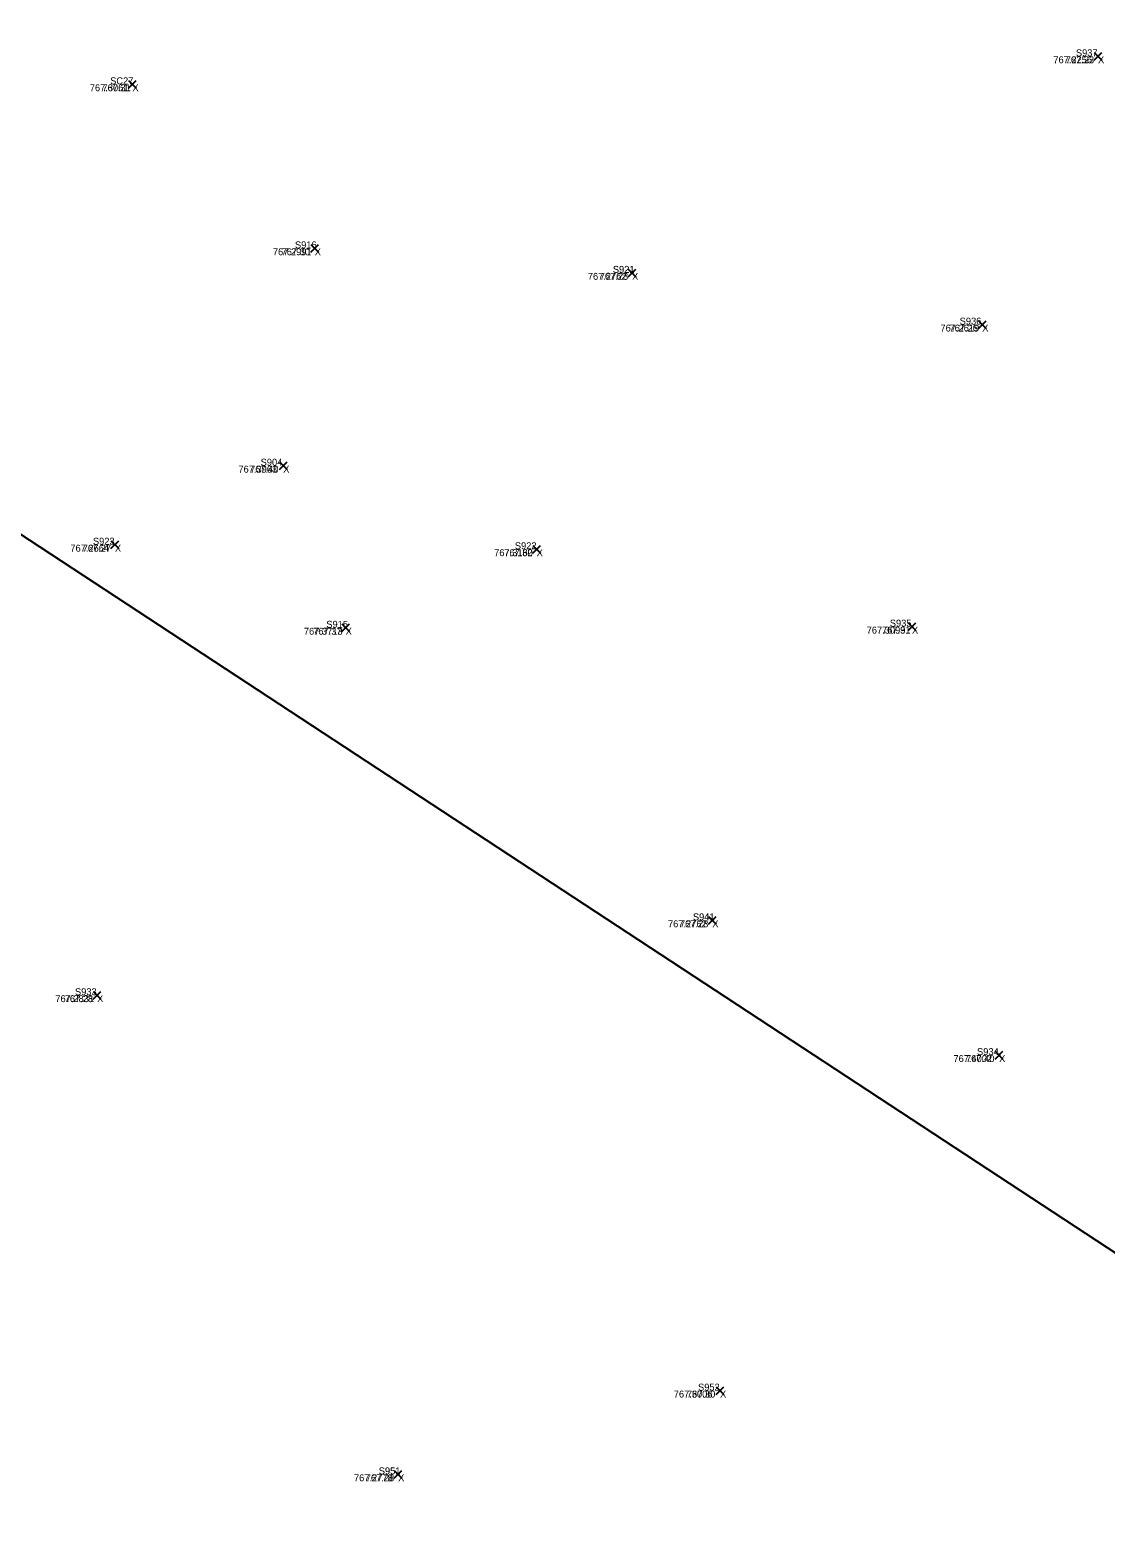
# Model space of a CAD drawing. Extents: x 1845019 to 1877956, y 680444 to 701081.
# Drawn here: x 1857694.08 to 1857703.38, y 694251.31 to 694264.34 of the extents above; entities that cross this region are included whole.
import ezdxf

# ---------------------------------------------------------------- set-up
doc = ezdxf.new("R2010")
doc.units = 0
for name, color, linetype in [('SV_X_CL_Survey_20', 7, 'Continuous'), ('SV_X_Random_Point', 7, 'Continuous'), ('SV_X_Text_Comment', 7, 'Continuous'), ('SV_X_Text_Elevation', 7, 'Continuous'), ('SV_X_Text_Name', 7, 'Continuous')]:
    doc.layers.add(name, color=color, linetype=linetype)

msp = doc.modelspace()

# ---------------------------------------------------------------- linework, layer by layer
at = {"layer": 'SV_X_CL_Survey_20'}
msp.add_line((1856038.267, 695346.314), (1858797.327, 693536.085), dxfattribs=at)
at = {"layer": 'SV_X_Random_Point'}
for p, q in [((1857703.277, 694264.085), (1857703.344, 694264.152)), ((1857703.277, 694264.152), (1857703.344, 694264.085)), ((1857703.277, 694264.085), (1857703.344, 694264.152)), ((1857703.277, 694264.152), (1857703.344, 694264.085)), ((1857694.927, 694263.843), (1857694.994, 694263.909)), ((1857694.927, 694263.909), (1857694.994, 694263.843)), ((1857694.927, 694263.843), (1857694.994, 694263.909)), ((1857694.927, 694263.909), (1857694.994, 694263.843)), ((1857696.504, 694262.425), (1857696.571, 694262.492)), ((1857696.504, 694262.492), (1857696.571, 694262.425)), ((1857696.504, 694262.425), (1857696.571, 694262.492)), ((1857696.504, 694262.492), (1857696.571, 694262.425)), ((1857699.248, 694262.212), (1857699.315, 694262.279)), ((1857699.248, 694262.279), (1857699.315, 694262.212)), ((1857699.248, 694262.212), (1857699.315, 694262.279)), ((1857699.248, 694262.279), (1857699.315, 694262.212)), ((1857702.276, 694261.765), (1857702.342, 694261.832)), ((1857702.276, 694261.832), (1857702.342, 694261.765)), ((1857702.276, 694261.765), (1857702.342, 694261.832)), ((1857702.276, 694261.832), (1857702.342, 694261.765)), ((1857696.232, 694260.546), (1857696.298, 694260.613)), ((1857696.232, 694260.613), (1857696.298, 694260.546)), ((1857696.232, 694260.546), (1857696.298, 694260.613)), ((1857696.232, 694260.613), (1857696.298, 694260.546)), ((1857694.776, 694259.863), (1857694.843, 694259.93)), ((1857694.776, 694259.93), (1857694.843, 694259.863)), ((1857694.776, 694259.863), (1857694.843, 694259.93)), ((1857694.776, 694259.93), (1857694.843, 694259.863)), ((1857698.423, 694259.823), (1857698.49, 694259.89)), ((1857698.423, 694259.89), (1857698.49, 694259.823)), ((1857698.423, 694259.823), (1857698.49, 694259.89)), ((1857698.423, 694259.89), (1857698.49, 694259.823)), ((1857696.771, 694259.145), (1857696.838, 694259.212)), ((1857696.771, 694259.212), (1857696.838, 694259.145)), ((1857696.771, 694259.145), (1857696.838, 694259.212)), ((1857696.771, 694259.212), (1857696.838, 694259.145)), ((1857701.668, 694259.154), (1857701.735, 694259.221)), ((1857701.668, 694259.221), (1857701.735, 694259.154)), ((1857701.668, 694259.154), (1857701.735, 694259.221)), ((1857701.668, 694259.221), (1857701.735, 694259.154)), ((1857699.942, 694256.616), (1857700.008, 694256.682)), ((1857699.942, 694256.682), (1857700.008, 694256.616)), ((1857699.942, 694256.616), (1857700.008, 694256.682)), ((1857699.942, 694256.682), (1857700.008, 694256.616)), ((1857694.623, 694255.968), (1857694.689, 694256.035)), ((1857694.623, 694256.035), (1857694.689, 694255.968)), ((1857694.623, 694255.968), (1857694.689, 694256.035)), ((1857694.623, 694256.035), (1857694.689, 694255.968)), ((1857702.422, 694255.45), (1857702.488, 694255.517)), ((1857702.422, 694255.517), (1857702.488, 694255.45)), ((1857702.422, 694255.45), (1857702.488, 694255.517)), ((1857702.422, 694255.517), (1857702.488, 694255.45)), ((1857700.009, 694252.55), (1857700.076, 694252.617)), ((1857700.009, 694252.617), (1857700.076, 694252.55)), ((1857700.009, 694252.55), (1857700.076, 694252.617)), ((1857700.009, 694252.617), (1857700.076, 694252.55)), ((1857697.225, 694251.826), (1857697.292, 694251.893)), ((1857697.225, 694251.893), (1857697.292, 694251.826)), ((1857697.225, 694251.826), (1857697.292, 694251.893)), ((1857697.225, 694251.893), (1857697.292, 694251.826))]:
    msp.add_line(p, q, dxfattribs=at)

# ---------------------------------------------------------------- texts
at = {"layer": 'SV_X_Text_Comment'}
for p in [(1857703.31, 694264.058), (1857694.961, 694263.816), (1857696.538, 694262.398), (1857699.282, 694262.186), (1857702.309, 694261.739), (1857696.265, 694260.519), (1857694.81, 694259.836), (1857698.457, 694259.797), (1857696.805, 694259.118), (1857701.702, 694259.128), (1857699.975, 694256.589), (1857694.656, 694255.942), (1857702.455, 694255.424), (1857700.042, 694252.524), (1857697.259, 694251.8)]:
    msp.add_text('X', height=0.06, dxfattribs=at).set_placement(p)
at = {"layer": 'SV_X_Text_Elevation'}
for s, p in [('767.2256', (1857702.924, 694264.058)), ('767.23', (1857703.031, 694264.058)), ('767.3061', (1857694.593, 694263.816)), ('767.31', (1857694.702, 694263.816)), ('767.2991', (1857696.176, 694262.398)), ('767.30', (1857696.251, 694262.398)), ('767.2762', (1857698.899, 694262.186)), ('767.28', (1857699.002, 694262.186)), ('767.2619', (1857701.948, 694261.739)), ('767.26', (1857702.026, 694261.739)), ('767.3963', (1857695.878, 694260.519)), ('767.40', (1857695.979, 694260.519)), ('767.2664', (1857694.425, 694259.836)), ('767.27', (1857694.531, 694259.836)), ('767.3160', (1857698.089, 694259.797)), ('767.32', (1857698.176, 694259.797)), ('767.3713', (1857696.444, 694259.118)), ('767.37', (1857696.524, 694259.118)), ('767.3099', (1857701.31, 694259.128)), ('767.31', (1857701.443, 694259.128)), ('767.2762', (1857699.592, 694256.589)), ('767.28', (1857699.695, 694256.589)), ('767.2831', (1857694.295, 694255.942)), ('767.28', (1857694.376, 694255.942)), ('767.4002', (1857702.06, 694255.424)), ('767.40', (1857702.169, 694255.424)), ('767.3006', (1857699.642, 694252.524)), ('767.30', (1857699.756, 694252.524)), ('767.2778', (1857696.877, 694251.8)), ('767.28', (1857696.979, 694251.8))]:
    msp.add_text(s, height=0.06, dxfattribs=at).set_placement(p)
at = {"layer": 'SV_X_Text_Name'}
for s, p in [('S937', (1857703.119, 694264.118)), ('S937', (1857703.119, 694264.118)), ('SC27', (1857694.769, 694263.876)), ('SC27', (1857694.769, 694263.876)), ('S916', (1857696.367, 694262.458)), ('S916', (1857696.367, 694262.458)), ('S921', (1857699.115, 694262.246)), ('S921', (1857699.116, 694262.246)), ('S936', (1857702.114, 694261.799)), ('S936', (1857702.114, 694261.799)), ('S904', (1857696.07, 694260.579)), ('S904', (1857696.07, 694260.579)), ('S923', (1857694.62, 694259.896)), ('S923', (1857694.62, 694259.896)), ('S922', (1857698.268, 694259.857)), ('S922', (1857698.268, 694259.857)), ('S915', (1857696.638, 694259.178)), ('S915', (1857696.638, 694259.178)), ('S935', (1857701.51, 694259.188)), ('S935', (1857701.51, 694259.188)), ('S941', (1857699.807, 694256.649)), ('S941', (1857699.808, 694256.649)), ('S933', (1857694.465, 694256.002)), ('S933', (1857694.465, 694256.002)), ('S934', (1857702.264, 694255.484)), ('S934', (1857702.264, 694255.484)), ('S952', (1857699.852, 694252.584)), ('S952', (1857699.852, 694252.584)), ('S951', (1857697.092, 694251.86)), ('S951', (1857697.091, 694251.86))]:
    msp.add_text(s, height=0.06, dxfattribs=at).set_placement(p)

doc.saveas('drawing.dxf')
